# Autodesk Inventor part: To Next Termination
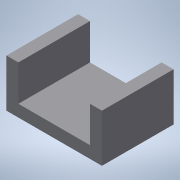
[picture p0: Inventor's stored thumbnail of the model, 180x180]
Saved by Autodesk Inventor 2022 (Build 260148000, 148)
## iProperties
Created: 2013-12
Part Number: To Next Termination
Material: Generic
Document SubType Name: Modeling
Designer: John
Density: 1 g/cm^3
Appearance: Default
Author: John
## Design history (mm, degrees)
sketch "Sketch1"
  geometry: L1 (0, 0)-(50.8, 0); L2 (50.8, 0)-(50.8, 25.4); L3 (50.8, 25.4)-(0, 25.4); L4 (0, 25.4)-(0, 0)
  constraints: 8 end point, 2 parallel, 1 horizontal, 1 perpendicular
  dimensions: "d0" = 50.8 distance of L3.end L2.end; "d1" = 25.4 distance of L2.end L1.end
extrude "Extrusion1" new body sketch "Sketch1" distance "d2" = 38.1; taper "d3" = 0 deg
sketch "Sketch2"
  geometry: L1 (0, 0)-(50.8, 0) reference; L2 (50.8, 0)-(50.8, 25.4) reference; L3 (50.8, 25.4)-(0, 25.4) reference; L4 (0, 25.4)-(0, 0) reference; L5 (6.35, 25.4)-(44.45, 25.4); L6 (44.45, 25.4)-(44.45, 6.35); L7 (44.45, 6.35)-(6.35, 6.35); L8 (6.35, 6.35)-(6.35, 25.4)
  constraints: 8 end point, 2 parallel, 1 horizontal, 1 perpendicular, 1 point on line
  dimensions: "d4" = 6.35 distance between parallel lines of L2 L6; "d5" = 6.35 distance between parallel lines of L1 L7 (= d4); "d6" = 6.35 distance between parallel lines of L4 L8 (= d4)
extrude "Extrusion2" cut sketch "Sketch2" extent not by distance; stored distance "d7" = 33.3375; taper "d8" = 0 deg
body "Solid1"
